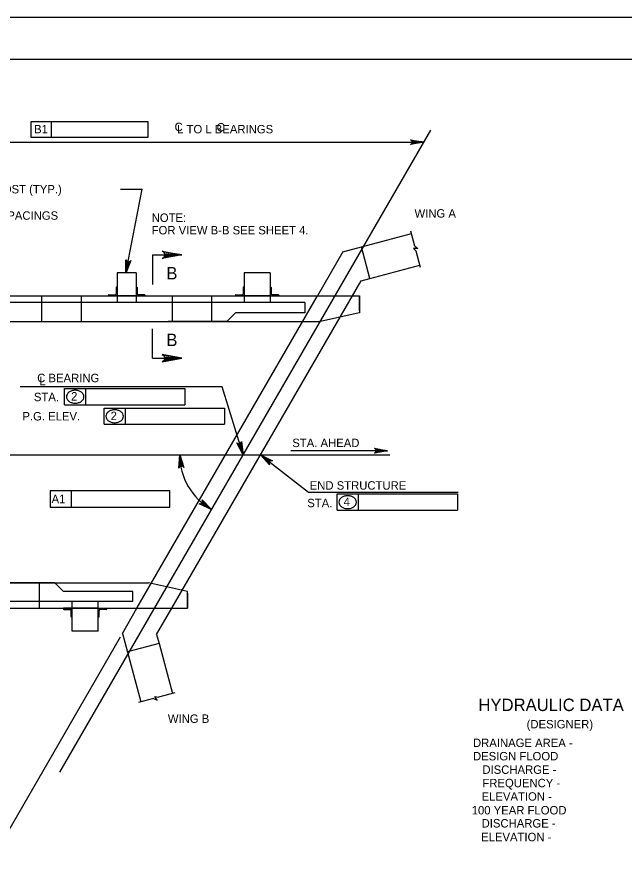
# Model space of a CAD drawing. Extents: x 638268 to 640277, y 295465 to 298435.
# Drawn here: x 638675.9 to 638891.9, y 298131.1 to 298435.5 of the extents above; entities that cross this region are included whole.
import ezdxf

# ---------------------------------------------------------------- set-up
doc = ezdxf.new("R2010")
doc.units = 0
for name, color, linetype in [('2', 7, 'Continuous'), ('3', 7, 'Continuous'), ('4', 7, 'Continuous'), ('PLT-BNDY', 7, 'Continuous')]:
    doc.layers.add(name, color=color, linetype=linetype)

msp = doc.modelspace()

# ---------------------------------------------------------------- linework, layer by layer
at = {"layer": '2'}
for p, q in [((638475.46, 298420.46), (639261.46, 298420.46)), ((638791.62, 298351.94), (638816.03, 298358.48)), ((638801.25, 298342.47), (638798.24, 298353.71)), ((638723.98, 298350.87), (638723.98, 298340.39)), ((638723.98, 298350.87), (638734.47, 298350.87)), ((638791.62, 298351.94), (638782.63, 298336.37)), ((638801.25, 298342.47), (638819.04, 298347.24)), ((638718.16, 298344.46), (638711.43, 298344.46)), ((638718.16, 298344.46), (638711.43, 298344.46)), ((638711.43, 298344.46), (638711.43, 298333.98)), ((638718.16, 298344.46), (638718.16, 298333.98)), ((638765.78, 298344.46), (638756.54, 298344.46)), ((638756.54, 298344.46), (638756.54, 298333.98)), ((638765.78, 298344.46), (638765.78, 298333.98)), ((638795.06, 298336.37), (638798.1, 298341.63)), ((638798.1, 298341.63), (638801.25, 298342.47)), ((638711.07, 298339.28), (638711.07, 298337.1)), ((638711.25, 298339.46), (638711.43, 298339.46)), ((638711.43, 298339.46), (638711.43, 298336.37)), ((638718.34, 298339.46), (638718.16, 298339.46)), ((638718.16, 298339.46), (638718.16, 298336.37)), ((638718.52, 298339.28), (638718.52, 298337.1)), ((638756.18, 298339.28), (638756.18, 298337.1)), ((638756.36, 298339.46), (638756.54, 298339.46)), ((638756.54, 298339.46), (638756.54, 298336.37)), ((638765.96, 298339.46), (638765.78, 298339.46)), ((638765.78, 298339.46), (638765.78, 298336.37)), ((638766.14, 298339.28), (638766.14, 298337.1)), ((638650.43, 298336.37), (638797.52, 298336.37)), ((638684.6, 298336.37), (638684.6, 298327.25)), ((638698.62, 298336.37), (638698.62, 298327.25)), ((638708.34, 298336.55), (638708.34, 298336.37)), ((638711.43, 298336.37), (638708.34, 298336.37)), ((638708.52, 298336.73), (638710.7, 298336.73)), ((638719.41, 298336.37), (638710.18, 298336.37)), ((638718.16, 298336.37), (638711.43, 298336.37)), ((638718.16, 298336.37), (638721.25, 298336.37)), ((638718.45, 298225.2), (638782.63, 298336.37)), ((638721.07, 298336.73), (638718.88, 298336.73)), ((638721.25, 298336.55), (638721.25, 298336.37)), ((638730.88, 298225.2), (638795.06, 298336.37)), ((638730.96, 298336.37), (638730.96, 298327.25)), ((638744.99, 298336.37), (638744.99, 298327.25)), ((638753.45, 298336.55), (638753.45, 298336.37)), ((638756.54, 298336.37), (638753.45, 298336.37)), ((638753.63, 298336.73), (638755.81, 298336.73)), ((638765.78, 298336.37), (638756.54, 298336.37)), ((638765.78, 298336.37), (638768.87, 298336.37)), ((638768.69, 298336.73), (638766.5, 298336.73)), ((638768.87, 298336.55), (638768.87, 298336.37)), ((638797.52, 298330.99), (638797.52, 298336.37)), ((638797.52, 298336.37), (638797.52, 298330.34)), ((638778.1, 298333.98), (638650.25, 298333.98)), ((638778.1, 298333.98), (638778.1, 298330.34)), ((638750.37, 298327.25), (638753.46, 298330.34)), ((638778.1, 298330.34), (638753.46, 298330.34)), ((638795.35, 298329.86), (638783.67, 298327.25)), ((638797.52, 298330.34), (638795.35, 298329.86)), ((638632.81, 298327.25), (638783.67, 298327.25)), ((638750.37, 298327.25), (638729.59, 298327.25)), ((638723.98, 298314.14), (638723.98, 298324.63)), ((638723.98, 298314.14), (638734.47, 298314.14)), ((638571.72, 298234.32), (638722.58, 298234.32)), ((638689.28, 298234.32), (638673.12, 298234.32)), ((638683.9, 298225.2), (638683.9, 298234.32)), ((638689.28, 298234.32), (638692.37, 298231.23)), ((638734.26, 298231.71), (638722.58, 298234.32)), ((638736.43, 298231.23), (638734.26, 298231.71)), ((638717.01, 298231.23), (638692.37, 298231.23)), ((638717.01, 298227.59), (638717.01, 298231.23)), ((638736.43, 298225.2), (638736.43, 298231.23)), ((638736.43, 298230.58), (638736.43, 298225.2)), ((638736.45, 298230.58), (638736.45, 298225.2)), ((638717.01, 298227.59), (638589.17, 298227.59)), ((638695.45, 298217.11), (638695.45, 298227.59)), ((638704.69, 298217.11), (638704.69, 298227.59)), ((638589.34, 298225.2), (638736.43, 298225.2)), ((638692.36, 298225.02), (638692.36, 298225.2)), ((638695.45, 298225.2), (638692.36, 298225.2)), ((638692.54, 298224.83), (638694.72, 298224.83)), ((638695.09, 298222.29), (638695.09, 298224.47)), ((638704.69, 298225.2), (638695.45, 298225.2)), ((638695.45, 298222.11), (638695.45, 298225.2)), ((638704.69, 298222.11), (638704.69, 298225.2)), ((638704.69, 298225.2), (638707.78, 298225.2)), ((638705.05, 298222.29), (638705.05, 298224.47)), ((638707.6, 298224.83), (638705.41, 298224.83)), ((638707.78, 298225.02), (638707.78, 298225.2)), ((638713.31, 298216.3), (638718.45, 298225.2)), ((638725.48, 298215.85), (638730.88, 298225.2)), ((638695.27, 298222.11), (638695.45, 298222.11)), ((638704.87, 298222.11), (638704.69, 298222.11)), ((638704.69, 298217.11), (638695.45, 298217.11)), ((638713.31, 298216.3), (638719.85, 298191.89)), ((638725.48, 298215.85), (638726.32, 298212.7)), ((638726.32, 298212.7), (638715.08, 298209.68)), ((638726.32, 298212.7), (638731.09, 298194.91))]:
    msp.add_line(p, q, dxfattribs=at)
for points in [[(638734.47, 298350.87), (638727.48, 298349.56), (638728.01, 298349.93), (638728.29, 298350.4), (638728.37, 298350.87), (638728.29, 298351.34), (638728.01, 298351.81), (638727.48, 298352.18), (638734.47, 298350.87), (638728.01, 298351.81), (638728.29, 298351.34), (638734.47, 298350.87), (638728.37, 298350.87), (638728.29, 298350.4), (638734.47, 298350.87), (638728.01, 298349.93)], [(638734.47, 298314.14), (638727.48, 298315.45), (638728.01, 298315.08), (638728.29, 298314.61), (638728.37, 298314.14), (638728.29, 298313.67), (638728.01, 298313.2), (638727.48, 298312.83), (638734.47, 298314.14), (638728.01, 298313.2), (638728.29, 298313.67), (638734.47, 298314.14), (638728.37, 298314.14), (638728.29, 298314.61), (638734.47, 298314.14), (638728.01, 298315.08)]]:
    msp.add_lwpolyline(points, dxfattribs=at)
for centre, radius, start, end in [((638711.25, 298339.28), 0.182, 90, 179.9984), ((638718.34, 298339.28), 0.182, 0.0016, 90), ((638756.36, 298339.28), 0.182, 90, 179.9984), ((638765.96, 298339.28), 0.182, 0.0016, 90), ((638708.52, 298336.55), 0.182, 90, 179.9984), ((638710.7, 298337.1), 0.364, 270, 359.9984), ((638718.88, 298337.1), 0.364, 180.0016, 270), ((638721.07, 298336.55), 0.182, 0.0016, 90), ((638753.63, 298336.55), 0.182, 90, 179.9984), ((638755.81, 298337.1), 0.364, 270, 359.9984), ((638766.5, 298337.1), 0.364, 180.0016, 270), ((638768.69, 298336.55), 0.182, 0.0016, 90), ((638692.54, 298225.02), 0.182, 180.0016, 270), ((638694.72, 298224.47), 0.364, 0.0016, 90), ((638705.41, 298224.47), 0.364, 90, 179.9984), ((638707.6, 298225.02), 0.182, 270, 359.9984), ((638695.27, 298222.29), 0.182, 180.0016, 270), ((638704.87, 298222.29), 0.182, 270, 359.9984)]:
    msp.add_arc(centre, radius, start, end, dxfattribs=at)
at = {"layer": '3'}
for p, q in [((638691.03, 298166.95), (638822.86, 298395.29)), ((638817.24, 298353.94), (638815.81, 298359.28)), ((638816.78, 298353.21), (638817.71, 298352.2)), ((638818.34, 298353.12), (638816.78, 298353.21)), ((638817.24, 298353.94), (638818.34, 298353.12)), ((638819.27, 298346.37), (638817.71, 298352.2)), ((638731.96, 298195.14), (638726.13, 298193.58)), ((638724.39, 298193.11), (638719.05, 298191.68)), ((638724.39, 298193.11), (638725.65, 298192.57)), ((638725.65, 298192.57), (638724.79, 298193.87)), ((638724.79, 298193.87), (638726.13, 298193.58))]:
    msp.add_line(p, q, dxfattribs=at)
at = {"layer": '4'}
for p, q in [((638680.88, 298398.35), (638688.11, 298398.35)), ((638680.88, 298392.59), (638680.88, 298398.35)), ((638688.11, 298392.59), (638688.11, 298398.35)), ((638688.11, 298398.35), (638722.4, 298398.35)), ((638722.4, 298398.35), (638722.4, 298392.59)), ((638628.98, 298391), (638820.39, 298391)), ((638722.4, 298392.59), (638680.88, 298392.59)), ((638712.63, 298374.31), (638720.36, 298374.31)), ((638714.52, 298344.45), (638720.36, 298374.31)), ((638748.74, 298304.01), (638676.93, 298304.01)), ((638692.75, 298303.39), (638700.33, 298303.39)), ((638692.75, 298297.62), (638692.75, 298303.39)), ((638700.33, 298297.62), (638700.33, 298303.39)), ((638700.33, 298303.39), (638735.51, 298303.39)), ((638735.51, 298303.39), (638735.51, 298297.62)), ((638756.2, 298279.83), (638748.74, 298304.01)), ((638692.75, 298297.62), (638735.51, 298297.62)), ((638706.8, 298296.42), (638714.37, 298296.42)), ((638706.8, 298290.66), (638706.8, 298296.42)), ((638714.37, 298290.66), (638714.37, 298296.42)), ((638714.37, 298296.42), (638749.56, 298296.42)), ((638749.56, 298296.42), (638749.56, 298290.66)), ((638706.8, 298290.66), (638749.56, 298290.66)), ((638807.54, 298281.23), (638773.18, 298281.23)), ((638523.29, 298279.83), (638808.3, 298279.83)), ((638762.42, 298279.83), (638779.49, 298266.49)), ((638687.63, 298267.05), (638687.62, 298261.14)), ((638687.63, 298267.05), (638695.19, 298267.05)), ((638695.19, 298261.14), (638695.19, 298267.05)), ((638695.19, 298267.05), (638730.15, 298267.05)), ((638730.14, 298261.14), (638730.15, 298267.05)), ((638779.49, 298266.49), (638832.67, 298266.49)), ((638789.59, 298265.87), (638797.17, 298265.87)), ((638789.59, 298260.11), (638789.59, 298265.87)), ((638797.17, 298260.11), (638797.17, 298265.87)), ((638797.17, 298265.87), (638832.35, 298265.87)), ((638832.35, 298265.87), (638832.35, 298260.11)), ((638687.62, 298261.14), (638730.14, 298261.14)), ((638789.59, 298260.11), (638832.35, 298260.11)), ((638712.54, 298214.97), (638667.6, 298137.13))]:
    msp.add_line(p, q, dxfattribs=at)
for points in [[(638820.39, 298391), (638815.73, 298390.12), (638816.08, 298390.37), (638816.27, 298390.68), (638816.32, 298391), (638816.27, 298391.31), (638816.08, 298391.62), (638815.73, 298391.87), (638820.39, 298391), (638816.08, 298391.62), (638816.27, 298391.31), (638820.39, 298391), (638816.32, 298391), (638816.27, 298390.68), (638820.39, 298391), (638816.08, 298390.37)], [(638714.52, 298344.45), (638714.56, 298349.19), (638714.73, 298348.79), (638715, 298348.55), (638715.3, 298348.44), (638715.62, 298348.43), (638715.96, 298348.55), (638716.27, 298348.86), (638714.52, 298344.45), (638715.96, 298348.55), (638715.62, 298348.43), (638714.52, 298344.45), (638715.3, 298348.44), (638715, 298348.55), (638714.52, 298344.45), (638714.73, 298348.79)], [(638756.2, 298279.83), (638753.99, 298284.03), (638754.34, 298283.76), (638754.69, 298283.67), (638755.01, 298283.71), (638755.29, 298283.86), (638755.53, 298284.12), (638755.66, 298284.54), (638756.2, 298279.83), (638755.53, 298284.12), (638755.29, 298283.86), (638756.2, 298279.83), (638755.01, 298283.71), (638754.69, 298283.67), (638756.2, 298279.83), (638754.34, 298283.76)], [(638807.54, 298281.23), (638802.88, 298280.36), (638803.24, 298280.61), (638803.43, 298280.92), (638803.48, 298281.23), (638803.43, 298281.55), (638803.24, 298281.86), (638802.88, 298282.11), (638807.54, 298281.23), (638803.24, 298281.86), (638803.43, 298281.55), (638807.54, 298281.23), (638803.48, 298281.23), (638803.43, 298280.92), (638807.54, 298281.23), (638803.24, 298280.61)], [(638733.67, 298279.83), (638735.1, 298275.31), (638734.81, 298275.64), (638734.48, 298275.78), (638734.16, 298275.8), (638733.86, 298275.71), (638733.57, 298275.48), (638733.36, 298275.1), (638733.67, 298279.83), (638733.57, 298275.48), (638733.86, 298275.71), (638733.67, 298279.83), (638734.16, 298275.8), (638734.48, 298275.78), (638733.67, 298279.83), (638734.81, 298275.64)], [(638762.42, 298279.83), (638766.63, 298277.65), (638766.19, 298277.67), (638765.86, 298277.54), (638765.62, 298277.33), (638765.47, 298277.05), (638765.43, 298276.69), (638765.55, 298276.27), (638762.42, 298279.83), (638765.43, 298276.69), (638765.47, 298277.05), (638762.42, 298279.83), (638765.62, 298277.33), (638765.86, 298277.54), (638762.42, 298279.83), (638766.19, 298277.67)], [(638744.94, 298260.31), (638740.64, 298262.33), (638741.08, 298262.32), (638741.41, 298262.47), (638741.64, 298262.69), (638741.78, 298262.97), (638741.81, 298263.33), (638741.67, 298263.75), (638744.94, 298260.31), (638741.81, 298263.33), (638741.78, 298262.97), (638744.94, 298260.31), (638741.64, 298262.69), (638741.41, 298262.47), (638744.94, 298260.31), (638741.08, 298262.32)]]:
    msp.add_lwpolyline(points, dxfattribs=at)
msp.add_lwpolyline([(638755.8, 298282.8), (638754.86, 298282.51), (638756.2, 298279.83)], close=True, dxfattribs=at)
for centre, radius, start, end in [((638695.81, 298300.08), 2.49, 126.3544, 150.6308), ((638696.25, 298299.48), 3.23, 106.9552, 126.3544), ((638696.54, 298298.54), 4.22, 90, 106.9552), ((638696.54, 298298.54), 4.22, 73.0448, 90), ((638696.83, 298299.48), 3.23, 53.6456, 73.0448), ((638697.27, 298300.08), 2.49, 29.3692, 53.6456), ((638695.13, 298300.46), 1.71, 150.6308, 180), ((638695.13, 298300.46), 1.71, 180, 209.3692), ((638695.81, 298300.84), 2.49, 209.3692, 233.6456), ((638696.25, 298301.44), 3.23, 233.6456, 253.0448), ((638696.83, 298301.44), 3.23, 286.9552, 306.3544), ((638697.27, 298300.84), 2.49, 306.3544, 330.6308), ((638697.95, 298300.46), 1.71, 0, 29.3692), ((638697.95, 298300.46), 1.71, 330.6308, 0), ((638696.54, 298302.39), 4.22, 253.0448, 270), ((638696.54, 298302.39), 4.22, 270, 286.9552), ((638710.29, 298292.51), 3.23, 106.9552, 126.3544), ((638710.58, 298291.57), 4.22, 90, 106.9552), ((638710.58, 298291.57), 4.22, 73.0448, 90), ((638710.87, 298292.51), 3.23, 53.6456, 73.0448), ((638709.17, 298293.49), 1.71, 150.6308, 180), ((638709.17, 298293.49), 1.71, 180, 209.3692), ((638709.85, 298293.11), 2.49, 126.3544, 150.6308), ((638709.85, 298293.88), 2.49, 209.3692, 233.6456), ((638711.31, 298293.11), 2.49, 29.3692, 53.6456), ((638711.31, 298293.88), 2.49, 306.3544, 330.6308), ((638711.99, 298293.49), 1.71, 0, 29.3692), ((638711.99, 298293.49), 1.71, 330.6308, 0), ((638710.29, 298294.47), 3.23, 233.6456, 253.0448), ((638710.58, 298295.42), 4.22, 253.0448, 270), ((638710.58, 298295.42), 4.22, 270, 286.9552), ((638710.87, 298294.47), 3.23, 286.9552, 306.3544), ((638756.21, 298279.83), 22.54, 179.9993, 239.9995), ((638793.08, 298261.96), 3.23, 106.9552, 126.3544), ((638793.37, 298261.02), 4.22, 90, 106.9552), ((638793.37, 298261.02), 4.22, 73.0448, 90), ((638793.66, 298261.96), 3.23, 53.6456, 73.0448), ((638791.97, 298262.94), 1.71, 150.6308, 180), ((638791.97, 298262.94), 1.71, 180, 209.3692), ((638792.64, 298262.56), 2.49, 126.3544, 150.6308), ((638792.64, 298263.32), 2.49, 209.3692, 233.6456), ((638794.1, 298262.56), 2.49, 29.3692, 53.6456), ((638794.1, 298263.32), 2.49, 306.3544, 330.6308), ((638794.78, 298262.94), 1.71, 0, 29.3692), ((638794.78, 298262.94), 1.71, 330.6308, 0), ((638793.08, 298263.92), 3.23, 233.6456, 253.0448), ((638793.37, 298264.87), 4.22, 253.0448, 270), ((638793.37, 298264.87), 4.22, 270, 286.9552), ((638793.66, 298263.92), 3.23, 286.9552, 306.3544)]:
    msp.add_arc(centre, radius, start, end, dxfattribs=at)
at = {"layer": 'PLT-BNDY'}
msp.add_lwpolyline([(638435.46, 298435.46), (639276.46, 298435.46), (639276.46, 297841.46), (638435.46, 297841.46)], close=True, dxfattribs=at)

# ---------------------------------------------------------------- texts
at = {"layer": '4'}
for s, height, p in [('B1', 3, (638681.94, 298394.11)), ('C', 3, (638731.85, 298394.91)), ('L TO L BEARINGS', 3, (638732.77, 298394.11)), ('C', 3, (638746.81, 298394.77)), ('GLULAM BRIDGE RAIL POST (TYP.)', 3, (638623.99, 298372.76)), ('FOR DIMENSIONS AND SPACINGS', 3, (638624.05, 298363.39)), ('NOTE:', 3, (638723.72, 298362.62)), ('WING A', 3, (638817.12, 298364.14)), ('FOR VIEW B-B SEE SHEET 4.', 3, (638723.72, 298358.18)), ('B', 4.43, (638728.92, 298318.44)), ('C BEARING', 3, (638683.04, 298305.62)), ('L', 3, (638683.86, 298304.56)), ('STA.', 3, (638681.87, 298298.87)), ('2', 3, (638695.09, 298299.11)), ('P.G. ELEV.', 3, (638677.78, 298292.01)), ('2', 3, (638709.13, 298292.14)), ('STA. AHEAD', 3, (638773.68, 298282.54)), ('END STRUCTURE', 3, (638779.87, 298267.4)), ('STA.', 3, (638779, 298261.16)), ('4', 3, (638791.92, 298261.59)), ('HYDRAULIC DATA', 4.4292, (638839.81, 298188.66)), ('WING B', 3, (638729.47, 298184.46)), ('(DESIGNER)', 3, (638856.95, 298182.5)), ('DRAINAGE AREA - ', 3, (638837.89, 298175.87)), ('DESIGN FLOOD  ', 3, (638837.89, 298171.12)), ('   DISCHARGE - ', 3, (638837.89, 298166.33)), ('   FREQUENCY - ', 3, (638837.89, 298161.56)), ('   ELEVATION - ', 3, (638837.61, 298156.79)), ('100 YEAR FLOOD', 3, (638837.44, 298151.9)), ('   DISCHARGE - ', 3, (638837.61, 298147.25)), ('   ELEVATION - ', 3, (638837.44, 298142.36))]:
    msp.add_text(s, height=height, dxfattribs=at).set_placement(p)
for s, height, rotation, p in [('B', 4.43, 360, (638728.92, 298342.15)), ('A1', 3, 359.9382, (638688.14, 298262.6))]:
    msp.add_text(s, height=height, rotation=rotation, dxfattribs=at).set_placement(p)

doc.saveas('drawing.dxf')
